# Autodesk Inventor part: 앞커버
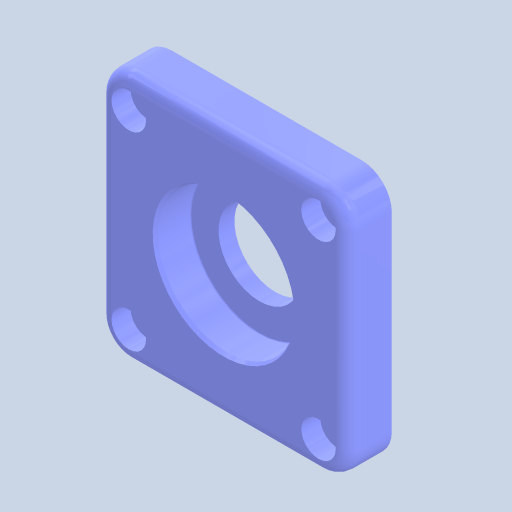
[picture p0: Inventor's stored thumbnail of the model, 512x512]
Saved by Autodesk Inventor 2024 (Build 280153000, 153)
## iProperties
Created: 2026-01
Part Number: 앞커버
Material: 알루미늄 6061
Document SubType Name: Modeling
Designer: 2-10
Density: 2.7 g/cm^3
Appearance: 기본값
Author: jhkim
Sending System: Autodesk Inventor 2026
Preprocessor: ST-DEVELOPER v20.1
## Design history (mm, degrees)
feature "솔리드1"
node "솔리드2"
